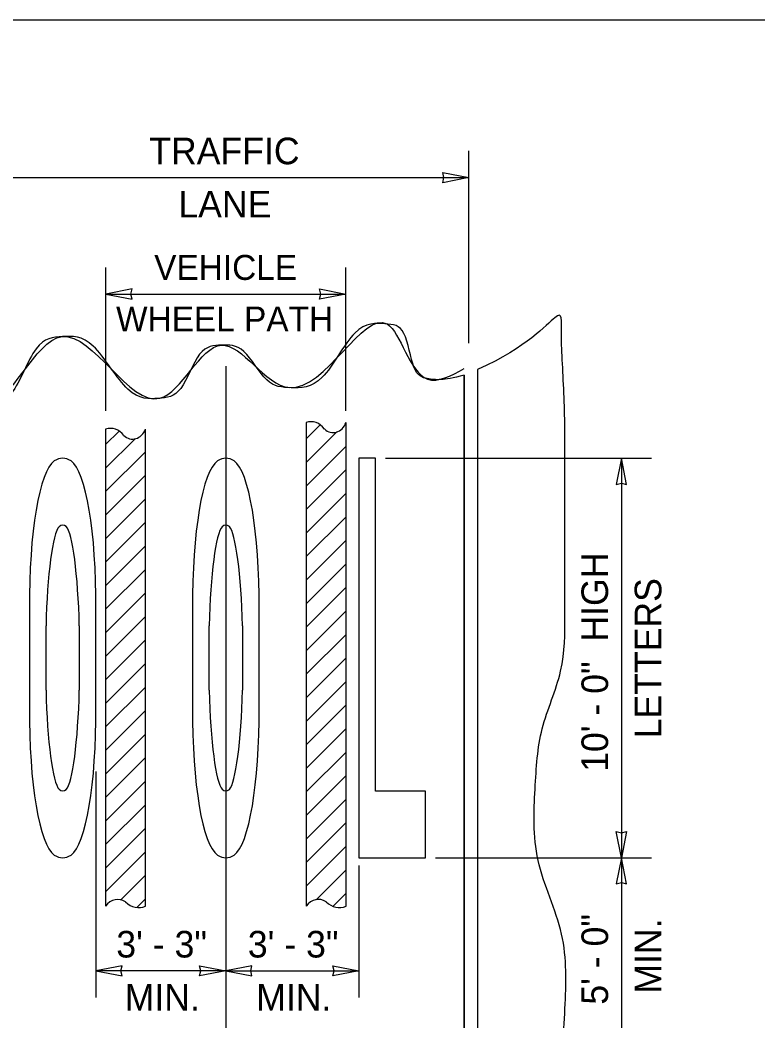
# Model space of a CAD drawing. Extents: x 99862 to 103151, y 100000 to 105076.
# Drawn here: x 100306 to 100749, y 104474 to 105076 of the extents above; entities that cross this region are included whole.
import ezdxf

# ---------------------------------------------------------------- set-up
doc = ezdxf.new("R2010")
doc.units = 0
for name, color, linetype in [('Level 1', 7, 'Continuous'), ('Level 15', 7, 'Continuous'), ('Level 20', 7, 'Continuous'), ('Level 3', 7, 'Continuous'), ('Level 6', 7, 'Continuous'), ('Level 8', 7, 'Continuous')]:
    doc.layers.add(name, color=color, linetype=linetype)

msp = doc.modelspace()

# ---------------------------------------------------------------- linework, layer by layer
at = {"layer": 'Level 1'}
msp.add_lwpolyline([(99862, 102999.5), (103151, 102999.5), (103151, 105075.5), (99862, 105075.5)], close=True, dxfattribs=at)
at = {"layer": 'Level 15'}
for p, q in [((100575.36, 104881.38), (100575.36, 104996.83)), ((100284.63, 104980.83), (100575.36, 104980.83)), ((100357.36, 104840.62), (100357.36, 104926.83)), ((100501.36, 104840.62), (100501.36, 104926.83)), ((100357.36, 104910.83), (100501.36, 104910.83)), ((100429.36, 104867.44), (100429.36, 104419.06)), ((100525.36, 104812.11), (100684.97, 104812.11)), ((100666.97, 104812.11), (100666.97, 104572.11)), ((100351.35, 104623.94), (100351.35, 104488.11)), ((100555.38, 104572.11), (100684.97, 104572.11)), ((100666.97, 104572.11), (100666.97, 104452.11)), ((100509.36, 104567.44), (100509.36, 104488.11)), ((100429.35, 104504.11), (100351.35, 104504.11)), ((100429.35, 104504.11), (100509.36, 104504.11))]:
    msp.add_line(p, q, dxfattribs=at)
for points in [[(100575.36, 104980.83), (100559.63, 104977.75), (100560.36, 104980.83), (100559.63, 104983.92)], [(100357.36, 104910.83), (100373.08, 104907.75), (100372.36, 104910.83), (100373.08, 104913.92)], [(100501.36, 104910.83), (100485.63, 104907.75), (100486.36, 104910.83), (100485.63, 104913.92)], [(100666.97, 104812.11), (100663.89, 104796.38), (100666.97, 104797.11), (100670.06, 104796.38)], [(100666.97, 104572.11), (100663.89, 104587.83), (100666.97, 104587.1), (100670.06, 104587.83)], [(100666.97, 104572.11), (100663.89, 104556.38), (100666.97, 104557.11), (100670.06, 104556.38)], [(100351.35, 104504.11), (100367.08, 104501.02), (100366.35, 104504.11), (100367.08, 104507.19)], [(100429.35, 104504.11), (100413.63, 104501.02), (100414.36, 104504.11), (100413.63, 104507.19)], [(100429.35, 104504.11), (100445.08, 104501.02), (100444.35, 104504.11), (100445.08, 104507.19)], [(100509.36, 104504.11), (100493.63, 104501.02), (100494.36, 104504.11), (100493.63, 104507.19)]]:
    msp.add_lwpolyline(points, close=True, dxfattribs=at)
at = {"layer": 'Level 3'}
msp.add_line((100572.63, 104239.72), (100572.63, 104862.08), dxfattribs=at)
msp.add_lwpolyline([(100580.63, 104865.45), (100580.63, 104251.2)], dxfattribs=at)
msp.add_spline([(99942.44, 104822.69), (99964.13, 104883.94), (100020.92, 104845.66), (100050.27, 104880.11), (100103.86, 104844.38), (100162.56, 104876.28), (100188.09, 104848.21), (100236.58, 104881.39), (100285.07, 104844.38), (100331.01, 104885.22), (100389.7, 104848.21), (100426.71, 104880.11), (100467.55, 104854.59), (100526.24, 104892.87), (100550.49, 104859.7), (100572.63, 104865.98)], degree=3, dxfattribs=at)
for points in [[(100572.63, 104862.08), (100565.49, 104860.05), (100558.06, 104859.05), (100550.49, 104859.7), (100541.57, 104862.25), (100537.59, 104891.99), (100526.24, 104892.87), (100506.89, 104894.37), (100487.29, 104853.94), (100467.55, 104854.59), (100453.98, 104855.04), (100440.17, 104880.64), (100426.71, 104880.11), (100413.05, 104879.58), (100402.73, 104849.24), (100389.7, 104848.21), (100371.2, 104846.74), (100349.09, 104886.25), (100331.01, 104885.22), (100314.99, 104884.3), (100301.12, 104844.83), (100285.07, 104844.38), (100269.13, 104843.94), (100252.89, 104880.81), (100236.58, 104881.39), (100220.87, 104881.95), (100203.86, 104846.74), (100188.09, 104848.21), (100177.9, 104849.16), (100173.07, 104875.52), (100162.56, 104876.28), (100144.07, 104877.63), (100122.88, 104843.97), (100103.86, 104844.38), (100085.53, 104844.78), (100067.33, 104880.6), (100050.27, 104880.11), (100038.28, 104879.77), (100031.44, 104847.84), (100020.92, 104845.66), (100005, 104842.36), (99971.76, 104905.46), (99964.13, 104883.94), (99956.9, 104863.52), (99949.67, 104843.11), (99942.44, 104822.69)], [(100614.77, 104239.24), (100614.04, 104271.68), (100613.31, 104304.13), (100612.67, 104336.53), (100611.71, 104385.44), (100630.92, 104433.49), (100633.09, 104482), (100635.06, 104526.23), (100612.85, 104570.49), (100615.22, 104614.71), (100617.1, 104649.77), (100633.09, 104683.97), (100633.09, 104719.35), (100633.09, 104734.66), (100633.09, 104749.98), (100633.09, 104765.29), (100633.09, 104806.97), (100633.09, 104848.66), (100629.93, 104890.34), (100633.09, 104905.94), (100610.77, 104879.08), (100580.63, 104865.45)]]:
    msp.add_open_spline(points, degree=3, dxfattribs=at)
at = {"layer": 'Level 6'}
for p, q in [((100580.63, 104865.36), (100580.63, 104251.04)), ((100477.63, 104823.74), (100486.08, 104832.19)), ((100357.13, 104820.37), (100365.21, 104828.44)), ((100357.13, 104806.23), (100374.82, 104823.91)), ((100477.63, 104809.6), (100495.99, 104827.96)), ((100477.63, 104795.46), (100501.63, 104819.46)), ((100357.13, 104792.08), (100381.13, 104816.08)), ((100477.63, 104781.31), (100501.63, 104805.31)), ((100357.13, 104777.94), (100381.13, 104801.94)), ((100357.13, 104763.8), (100381.13, 104787.8)), ((100477.63, 104767.17), (100501.63, 104791.17)), ((100477.63, 104753.03), (100501.63, 104777.03)), ((100357.13, 104749.66), (100381.13, 104773.66)), ((100477.63, 104738.89), (100501.63, 104762.89)), ((100357.13, 104735.51), (100381.13, 104759.51)), ((100357.13, 104721.37), (100381.13, 104745.37)), ((100477.63, 104724.74), (100501.63, 104748.74)), ((100477.63, 104710.6), (100501.63, 104734.6)), ((100357.13, 104707.23), (100381.13, 104731.23)), ((100477.63, 104696.46), (100501.63, 104720.46)), ((100357.13, 104693.09), (100381.13, 104717.09)), ((100357.13, 104678.95), (100381.13, 104702.95)), ((100477.63, 104682.32), (100501.63, 104706.32)), ((100477.63, 104668.18), (100501.63, 104692.18)), ((100357.13, 104664.8), (100381.13, 104688.8)), ((100357.13, 104650.66), (100381.13, 104674.66)), ((100477.63, 104654.03), (100501.63, 104678.03)), ((100357.13, 104636.52), (100381.13, 104660.52)), ((100477.63, 104639.89), (100501.63, 104663.89)), ((100477.63, 104625.75), (100501.63, 104649.75)), ((100357.13, 104622.38), (100381.13, 104646.38)), ((100357.13, 104608.24), (100381.13, 104632.24)), ((100477.63, 104611.61), (100501.63, 104635.61)), ((100477.63, 104597.47), (100501.63, 104621.47)), ((100357.13, 104594.09), (100381.13, 104618.09)), ((100477.63, 104583.32), (100501.63, 104607.32)), ((100357.13, 104579.95), (100381.13, 104603.95)), ((100357.13, 104565.81), (100381.13, 104589.81)), ((100477.63, 104569.18), (100501.63, 104593.18)), ((100477.63, 104555.04), (100501.63, 104579.04)), ((100357.13, 104551.67), (100381.13, 104575.67)), ((100483.56, 104546.82), (100501.63, 104564.9)), ((100366.34, 104546.74), (100381.13, 104561.52)), ((100376, 104542.25), (100381.13, 104547.38)), ((100493.78, 104542.9), (100501.63, 104550.75))]:
    msp.add_line(p, q, dxfattribs=at)
for points in [[(100572.63, 104862.08), (100572.63, 104238.98)], [(100357.13, 104829.58), (100357.13, 104543)], [(100381.13, 104543), (100381.13, 104829.58)], [(100477.63, 104833.58), (100477.63, 104543.01)], [(100501.63, 104543.01), (100501.63, 104833.58)]]:
    msp.add_lwpolyline(points, dxfattribs=at)
for centre, major_axis, ratio, start_param, end_param in [((100480.63, 104819.89), (0, -14.21), 0.779509, 2.334921, 3.41576), ((100360.13, 104816.09), (0, -14.02), 0.790336, 2.334921, 3.41576), ((100373.33, 104834.84), (0, -11.19), 0.790336, 5.65539, 7.364579), ((100493.83, 104838.91), (0, -11.35), 0.779509, 5.65539, 7.364579), ((100364.47, 104534.14), (0, -12.83), 0.790336, 2.66324, 3.950242), ((100484.97, 104534.03), (0, -13.01), 0.779509, 2.66324, 3.950242), ((100376.97, 104558.18), (0, -16.07), 0.790336, 5.61869, 6.617383), ((100497.47, 104558.4), (0, -16.3), 0.779509, 5.61869, 6.617383)]:
    msp.add_ellipse(centre, major_axis=major_axis, ratio=ratio, start_param=start_param, end_param=end_param, dxfattribs=at)
at = {"layer": 'Level 8'}
for p, q in [((100519.36, 104812.11), (100509.36, 104812.11)), ((100509.36, 104812.11), (100509.36, 104572.11)), ((100519.36, 104612.11), (100519.36, 104812.11)), ((100311.37, 104721.48), (100311.37, 104692.11)), ((100351.35, 104692.11), (100351.35, 104721.48)), ((100409.37, 104721.48), (100409.37, 104692.11)), ((100449.35, 104692.11), (100449.35, 104721.48)), ((100321.36, 104692.11), (100321.36, 104711.48)), ((100341.36, 104711.48), (100341.36, 104692.11)), ((100419.36, 104692.11), (100419.36, 104711.48)), ((100439.36, 104711.48), (100439.36, 104692.11)), ((100311.37, 104692.11), (100311.37, 104662.73)), ((100321.36, 104672.73), (100321.36, 104692.11)), ((100341.36, 104692.11), (100341.36, 104672.73)), ((100351.35, 104662.73), (100351.35, 104692.11)), ((100409.37, 104692.11), (100409.37, 104662.73)), ((100419.36, 104672.73), (100419.36, 104692.11)), ((100439.36, 104692.11), (100439.36, 104672.73)), ((100449.35, 104662.73), (100449.35, 104692.11)), ((100549.36, 104612.11), (100519.36, 104612.11)), ((100549.36, 104572.11), (100549.36, 104612.11)), ((100509.36, 104572.11), (100518.11, 104572.11)), ((100518.11, 104572.11), (100519.36, 104572.11)), ((100519.36, 104572.11), (100549.36, 104572.11))]:
    msp.add_line(p, q, dxfattribs=at)
for points in [[(100549.36, 104612.11), (100519.36, 104612.11), (100519.36, 104812.11), (100509.36, 104812.11), (100509.36, 104572.11), (100518.11, 104572.11), (100519.36, 104572.11), (100549.36, 104572.11), (100549.36, 104612.11)], [(100549.36, 104612.11), (100519.36, 104612.11), (100519.36, 104812.11), (100509.36, 104812.11), (100509.36, 104572.11), (100518.11, 104572.11), (100519.36, 104572.11), (100549.36, 104572.11), (100549.36, 104612.11)], [(100311.37, 104721.48), (100311.37, 104692.11), (100311.37, 104662.73)], [(100311.37, 104721.48), (100311.37, 104692.11), (100311.37, 104662.73)], [(100351.35, 104662.73), (100351.35, 104692.11), (100351.35, 104721.48)], [(100351.35, 104662.73), (100351.35, 104692.11), (100351.35, 104721.48)], [(100409.37, 104721.48), (100409.37, 104692.11), (100409.37, 104662.73)], [(100409.37, 104721.48), (100409.37, 104692.11), (100409.37, 104662.73)], [(100449.35, 104662.73), (100449.35, 104692.11), (100449.35, 104721.48)], [(100449.35, 104662.73), (100449.35, 104692.11), (100449.35, 104721.48)], [(100321.36, 104672.73), (100321.36, 104692.11), (100321.36, 104711.48)], [(100321.36, 104672.73), (100321.36, 104692.11), (100321.36, 104711.48)], [(100341.36, 104711.48), (100341.36, 104692.11), (100341.36, 104672.73)], [(100341.36, 104711.48), (100341.36, 104692.11), (100341.36, 104672.73)], [(100419.36, 104672.73), (100419.36, 104692.11), (100419.36, 104711.48)], [(100419.36, 104672.73), (100419.36, 104692.11), (100419.36, 104711.48)], [(100439.36, 104711.48), (100439.36, 104692.11), (100439.36, 104672.73)], [(100439.36, 104711.48), (100439.36, 104692.11), (100439.36, 104672.73)]]:
    msp.add_lwpolyline(points, dxfattribs=at)
for centre, major_axis, ratio, start_param, end_param in [((100331.36, 104711.9), (2.5, -99.58), 0.19927, 3.270148, 4.611013), ((100331.36, 104711.9), (2.5, -99.58), 0.19927, 3.270148, 4.611013), ((100326.36, 104601.72), (-5.24, -210.38), 0.19927, 3.02647, 3.266464), ((100326.36, 104601.72), (-5.24, -210.38), 0.19927, 3.02647, 3.266464), ((100331.37, 104711.95), (-2.48, -99.53), 0.19927, 1.671693, 3.012646), ((100331.37, 104711.95), (-2.48, -99.53), 0.19927, 1.671693, 3.012646), ((100429.36, 104711.9), (2.5, -99.58), 0.19927, 3.270148, 4.611013), ((100429.36, 104711.9), (2.5, -99.58), 0.19927, 3.270148, 4.611013), ((100424.36, 104601.72), (-5.24, -210.38), 0.19927, 3.02647, 3.266464), ((100424.36, 104601.72), (-5.24, -210.38), 0.19927, 3.02647, 3.266464), ((100429.37, 104711.95), (-2.48, -99.53), 0.19927, 1.671693, 3.012646), ((100429.37, 104711.95), (-2.48, -99.53), 0.19927, 1.671693, 3.012646), ((100328.7, 104711.32), (-1.41, -60.17), 0.122012, 3.268533, 4.71248), ((100328.7, 104711.32), (-1.41, -60.17), 0.122012, 3.268533, 4.71248), ((100327.38, 104598.38), (-4.06, -173.57), 0.122012, 3.042541, 3.248082), ((100327.38, 104598.38), (-4.06, -173.57), 0.122012, 3.042541, 3.248082), ((100334.02, 104711.32), (1.41, -60.17), 0.122012, 1.570705, 3.018849), ((100334.02, 104711.32), (1.41, -60.17), 0.122012, 1.570705, 3.018849), ((100426.7, 104711.32), (-1.41, -60.17), 0.122012, 3.268533, 4.71248), ((100426.7, 104711.32), (-1.41, -60.17), 0.122012, 3.268533, 4.71248), ((100425.38, 104598.38), (-4.06, -173.57), 0.122012, 3.042541, 3.248082), ((100425.38, 104598.38), (-4.06, -173.57), 0.122012, 3.042541, 3.248082), ((100432.02, 104711.32), (1.41, -60.17), 0.122012, 1.570705, 3.018849), ((100432.02, 104711.32), (1.41, -60.17), 0.122012, 1.570705, 3.018849), ((100328.7, 104672.9), (1.41, -60.17), 0.122012, 4.712298, 6.156245), ((100328.7, 104672.9), (1.41, -60.17), 0.122012, 4.712298, 6.156245), ((100334.02, 104672.9), (-1.41, -60.17), 0.122012, 0.122744, 1.570888), ((100334.02, 104672.9), (-1.41, -60.17), 0.122012, 0.122744, 1.570888), ((100426.7, 104672.9), (1.41, -60.17), 0.122012, 4.712298, 6.156245), ((100426.7, 104672.9), (1.41, -60.17), 0.122012, 4.712298, 6.156245), ((100432.02, 104672.9), (-1.41, -60.17), 0.122012, 0.122744, 1.570888), ((100432.02, 104672.9), (-1.41, -60.17), 0.122012, 0.122744, 1.570888), ((100331.36, 104672.31), (-2.5, -99.58), 0.19927, 4.813765, 6.15463), ((100331.36, 104672.31), (-2.5, -99.58), 0.19927, 4.813765, 6.15463), ((100331.37, 104672.27), (2.48, -99.53), 0.19927, 0.128946, 1.4699), ((100331.37, 104672.27), (2.48, -99.53), 0.19927, 0.128946, 1.4699), ((100429.36, 104672.31), (-2.5, -99.58), 0.19927, 4.813765, 6.15463), ((100429.36, 104672.31), (-2.5, -99.58), 0.19927, 4.813765, 6.15463), ((100429.37, 104672.27), (2.48, -99.53), 0.19927, 0.128946, 1.4699), ((100429.37, 104672.27), (2.48, -99.53), 0.19927, 0.128946, 1.4699), ((100327.38, 104785.84), (4.06, -173.57), 0.122012, 6.176696, 6.382237), ((100327.38, 104785.84), (4.06, -173.57), 0.122012, 6.176696, 6.382237), ((100425.38, 104785.84), (4.06, -173.57), 0.122012, 6.176696, 6.382237), ((100425.38, 104785.84), (4.06, -173.57), 0.122012, 6.176696, 6.382237), ((100326.36, 104782.49), (5.24, -210.38), 0.19927, 6.158314, 6.398307), ((100326.36, 104782.49), (5.24, -210.38), 0.19927, 6.158314, 6.398307), ((100424.36, 104782.49), (5.24, -210.38), 0.19927, 6.158314, 6.398307), ((100424.36, 104782.49), (5.24, -210.38), 0.19927, 6.158314, 6.398307)]:
    msp.add_ellipse(centre, major_axis=major_axis, ratio=ratio, start_param=start_param, end_param=end_param, dxfattribs=at)

# ---------------------------------------------------------------- texts
at = {"layer": 'Level 20'}
for s, height, rotation, p in [('TRAFFIC', 16, 360, (100383.36, 104988.83)), ('LANE', 16, 360, (100400.85, 104956.83)), ('VEHICLE', 15, 360, (100386.34, 104919.33)), ('WHEEL PATH', 15, 360, (100363.42, 104888.33)), ('10\' - 0"  HIGH', 16, 90, (100658.97, 104623.69)), ('LETTERS', 16, 90, (100690.97, 104643.81)), ('5\' - 0"', 16, 90, (100658.97, 104483.77)), ('3\' - 3"', 16, 360, (100363.57, 104512.11)), ('3\' - 3"', 16, 360, (100442.57, 104512.11)), ('MIN.', 16, 90, (100690.97, 104490.38)), ('MIN.', 16, 360, (100368.63, 104480.11)), ('MIN.', 16, 360, (100447.63, 104480.11))]:
    msp.add_text(s, height=height, rotation=rotation, dxfattribs=at).set_placement(p)

doc.saveas('drawing.dxf')
